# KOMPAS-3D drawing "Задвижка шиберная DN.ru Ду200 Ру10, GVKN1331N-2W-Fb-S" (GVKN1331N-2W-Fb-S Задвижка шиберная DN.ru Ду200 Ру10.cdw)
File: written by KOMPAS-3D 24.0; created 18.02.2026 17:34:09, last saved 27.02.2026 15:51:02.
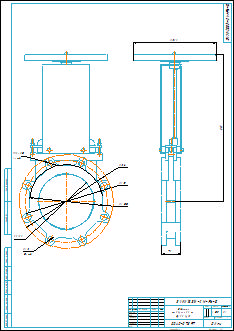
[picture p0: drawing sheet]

Document properties: art: D040-07897; Автор: R2D2; Форматы листов документа: A2; Полное имя файла: GVKN1331N-2W-Fb-S Задвижка шиберная DN.ru Ду200 Ру10.m3d; Масса: 26.5; Наименование: Задвижка шиберная DN.ru Ду200 Ру10; Количество листов документа: 1; Примечание: D040-07897

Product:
- Part/product: Задвижка шиберная DN.ru Ду200 Ру10  | designation GVKN1331N-2W-Fb-S
    Масса: 26.5
    Раздел спецификации: Прочие изделия
    Форматы листов документа: A2
    Примечание: D040-07897
    additional columns: D040-07897

Views: Вид 1, Спереди, Проекционный вид 2
Referenced files in E:\Работа\Зайцев\GVKN1331N-2W-Fb-S Задвижка шиберная DN.ru Ду50-300 Ру10\DN200\: GVKN1331N-2W-Fb-S Задвижка шиберная DN.ru Ду200 Ру10.m3d
Referenced files in E:\Работа\Зайцев\Для компаса\: чертеж DN.ru.cdt
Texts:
  GVKN1331N-2W-Fb-S
  чертеж DN.ru.cdt
  Задвижка
  шиберная DN.ru
  Ду200 Ру10
  prop
  Задвижка шиберная DN.ru Ду200 Ру10
  GVKN1331N-2W-Fb-S Задвижка шиберная DN.ru Ду200 Ру10
Dimensions and other numbers on the sheet: 0; 3; 2; 4; 295; 266; 200; 23; 6 отв.; 20; 2 отв.; 70; 531; 300; 340; 1:2; 1; 26,5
